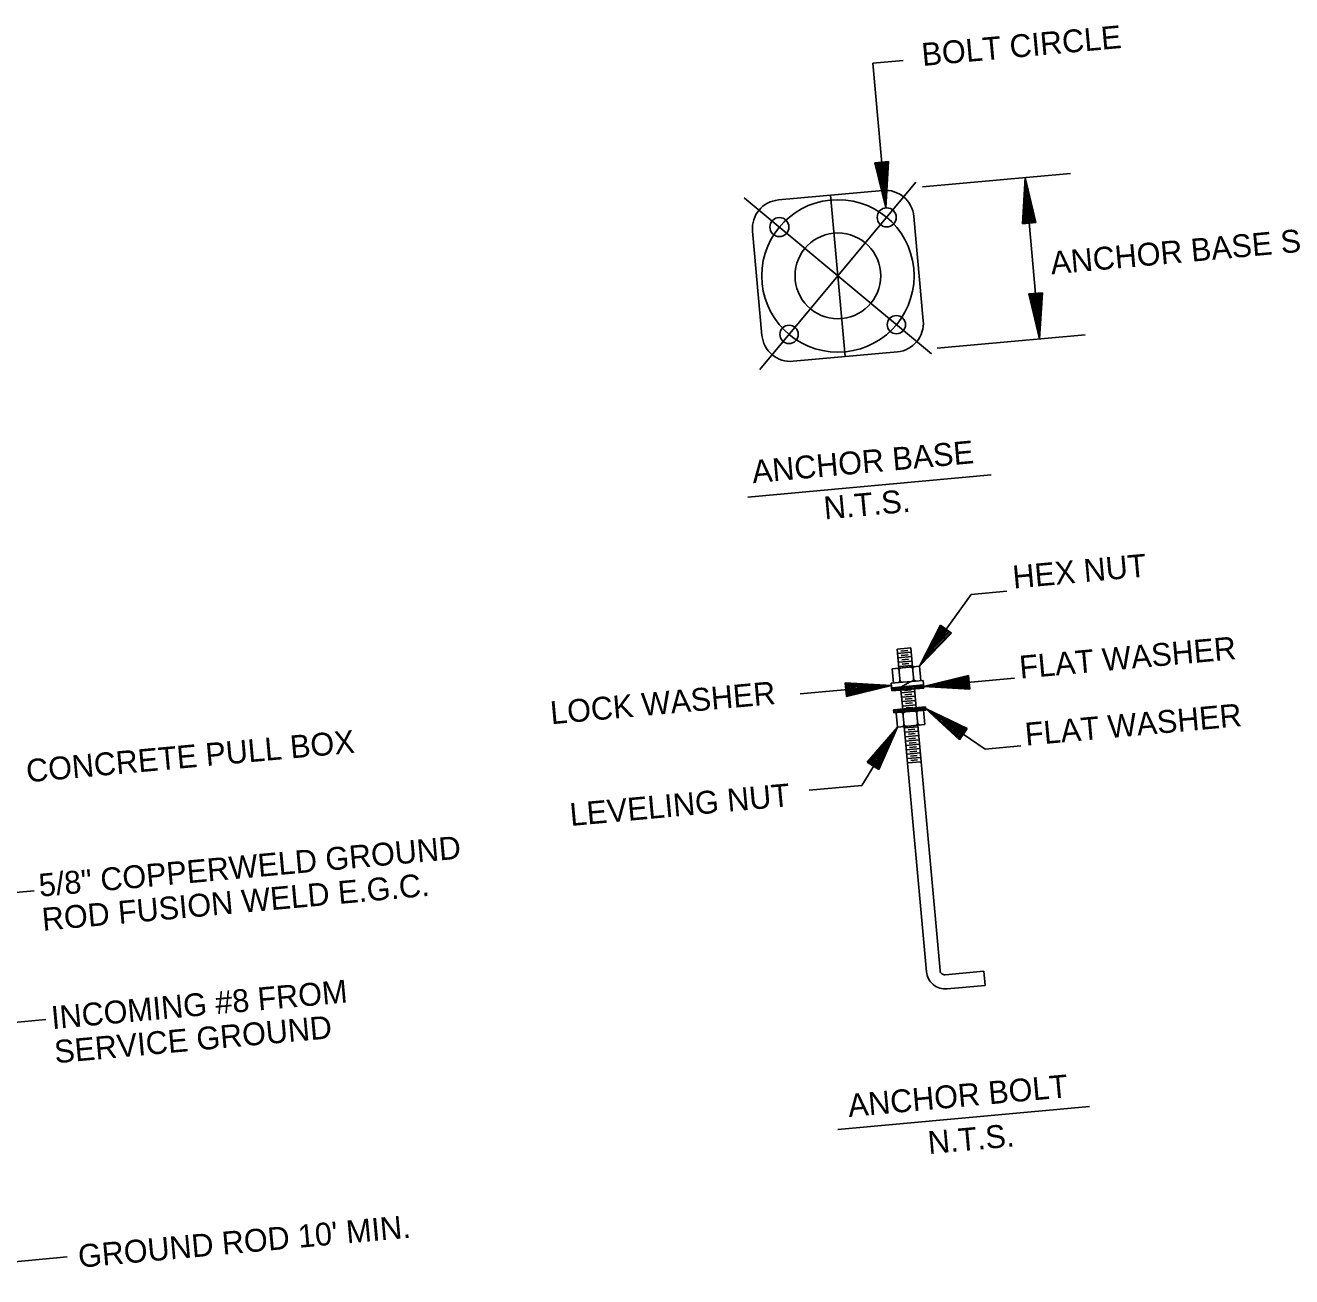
# Model space of a CAD drawing. Extents: x 1277218 to 1279252, y 196860 to 197529.
# Drawn here: x 1278535.3 to 1278789.6, y 197241.2 to 197492.4 of the extents above; entities that cross this region are included whole.
import ezdxf

# ---------------------------------------------------------------- set-up
doc = ezdxf.new("R2010")
doc.units = 0
doc.layers.add('R_Point Sym', color=7, linetype='Continuous')

msp = doc.modelspace()

# ---------------------------------------------------------------- linework, layer by layer
at = {"layer": 'R_Point Sym'}
for p, q in [((1278705.47, 197484.84), (1278711.6, 197485.39)), ((1278708.1, 197455.79), (1278705.47, 197484.84)), ((1278708.65, 197465.06), (1278705.91, 197464.81)), ((1278705.91, 197464.81), (1278708.1, 197455.79)), ((1278706.13, 197464.83), (1278707.97, 197457.32)), ((1278706.37, 197464.85), (1278707.82, 197458.89)), ((1278706.6, 197464.87), (1278707.69, 197460.41)), ((1278706.83, 197464.89), (1278707.55, 197461.96)), ((1278707.06, 197464.91), (1278707.41, 197463.49)), ((1278707.49, 197464.95), (1278707.41, 197463.49)), ((1278707.72, 197464.97), (1278707.55, 197461.96)), ((1278707.96, 197464.99), (1278707.69, 197460.41)), ((1278708.19, 197465.01), (1278707.82, 197458.89)), ((1278708.42, 197465.04), (1278707.97, 197457.32)), ((1278708.65, 197465.06), (1278708.1, 197455.79)), ((1278682.8, 197423.33), (1278714.16, 197460.94)), ((1278715.49, 197460), (1278745.2, 197462.69)), ((1278735.52, 197452.6), (1278736.06, 197461.86)), ((1278736.06, 197461.86), (1278738.99, 197429.48)), ((1278738.26, 197452.84), (1278736.06, 197461.86)), ((1278686.54, 197457.37), (1278707.49, 197459.27)), ((1278735.74, 197452.62), (1278736.2, 197460.33)), ((1278735.98, 197452.64), (1278736.34, 197458.76)), ((1278738.03, 197452.82), (1278736.2, 197460.33)), ((1278737.8, 197452.8), (1278736.34, 197458.76)), ((1278717.28, 197426.46), (1278679.68, 197457.81)), ((1278697.01, 197458.32), (1278699.95, 197425.94)), ((1278736.21, 197452.66), (1278736.48, 197457.24)), ((1278737.57, 197452.78), (1278736.48, 197457.24)), ((1278713.72, 197454.08), (1278715.62, 197433.13)), ((1278736.44, 197452.68), (1278736.62, 197455.69)), ((1278737.33, 197452.76), (1278736.62, 197455.69)), ((1278736.67, 197452.7), (1278736.76, 197454.16)), ((1278737.1, 197452.74), (1278736.76, 197454.16)), ((1278683.24, 197430.19), (1278681.34, 197451.14)), ((1278735.52, 197452.6), (1278738.26, 197452.84)), ((1278739.54, 197438.75), (1278736.79, 197438.5)), ((1278736.79, 197438.5), (1278738.99, 197429.48)), ((1278737.02, 197438.52), (1278738.85, 197431.01)), ((1278737.25, 197438.54), (1278738.71, 197432.58)), ((1278737.48, 197438.56), (1278738.57, 197434.1)), ((1278737.72, 197438.58), (1278738.43, 197435.65)), ((1278737.95, 197438.61), (1278738.29, 197437.18)), ((1278738.38, 197438.64), (1278738.29, 197437.18)), ((1278738.61, 197438.66), (1278738.43, 197435.65)), ((1278738.84, 197438.69), (1278738.57, 197434.1)), ((1278739.07, 197438.71), (1278738.71, 197432.58)), ((1278739.31, 197438.73), (1278738.85, 197431.01)), ((1278739.54, 197438.75), (1278738.99, 197429.48)), ((1278718.42, 197427.62), (1278748.13, 197430.31)), ((1278689.47, 197424.99), (1278710.42, 197426.89)), ((1278729.27, 197402.17), (1278680.42, 197397.74)), ((1278714.86, 197363.77), (1278725.24, 197378.19)), ((1278725.24, 197378.19), (1278732.39, 197378.84)), ((1278719.08, 197372.04), (1278714.86, 197363.77)), ((1278719.27, 197371.91), (1278715.75, 197365.02)), ((1278721.32, 197370.44), (1278719.08, 197372.04)), ((1278721.32, 197370.44), (1278714.86, 197363.77)), ((1278721.13, 197370.57), (1278715.75, 197365.02)), ((1278719.46, 197371.77), (1278716.67, 197366.3)), ((1278720.94, 197370.71), (1278716.67, 197366.3)), ((1278719.65, 197371.64), (1278717.56, 197367.55)), ((1278720.76, 197370.84), (1278717.56, 197367.55)), ((1278719.84, 197371.5), (1278718.47, 197368.81)), ((1278720.56, 197370.98), (1278718.47, 197368.81)), ((1278720.03, 197371.36), (1278719.36, 197370.06)), ((1278720.38, 197371.11), (1278719.36, 197370.06)), ((1278710.4, 197367.21), (1278713.14, 197367.46)), ((1278710.75, 197363.4), (1278710.4, 197367.21)), ((1278711.13, 197366.81), (1278712.5, 197366.94)), ((1278713.49, 197363.65), (1278713.14, 197367.46)), ((1278710.48, 197366.33), (1278713.22, 197366.58)), ((1278710.56, 197365.45), (1278713.3, 197365.7)), ((1278710.64, 197364.57), (1278713.38, 197364.82)), ((1278711.21, 197365.94), (1278712.58, 197366.06)), ((1278711.29, 197365.06), (1278712.66, 197365.18)), ((1278711.37, 197364.18), (1278712.74, 197364.3)), ((1278709.37, 197363.28), (1278714.86, 197363.77)), ((1278709.64, 197360.39), (1278709.37, 197363.28)), ((1278710.72, 197363.69), (1278713.46, 197363.94)), ((1278711.01, 197360.51), (1278710.75, 197363.4)), ((1278713.75, 197360.76), (1278713.49, 197363.65)), ((1278715.12, 197360.89), (1278714.86, 197363.77)), ((1278724.71, 197361.9), (1278715.69, 197359.7)), ((1278724.96, 197359.16), (1278724.71, 197361.9)), ((1278690.94, 197358.23), (1278709.22, 197359.89)), ((1278699.95, 197360.43), (1278709.22, 197359.89)), ((1278699.95, 197360.43), (1278700.2, 197357.69)), ((1278699.97, 197360.2), (1278707.69, 197359.75)), ((1278700, 197359.97), (1278706.12, 197359.61)), ((1278700.02, 197359.74), (1278704.6, 197359.47)), ((1278700.04, 197359.5), (1278703.05, 197359.33)), ((1278700.06, 197359.27), (1278701.52, 197359.19)), ((1278700.1, 197358.84), (1278701.52, 197359.19)), ((1278700.12, 197358.61), (1278703.05, 197359.33)), ((1278700.14, 197358.38), (1278704.6, 197359.47)), ((1278700.16, 197358.15), (1278706.12, 197359.61)), ((1278700.18, 197357.92), (1278707.69, 197359.75)), ((1278700.2, 197357.69), (1278709.22, 197359.89)), ((1278709.18, 197360.35), (1278715.58, 197360.93)), ((1278709.32, 197358.82), (1278709.18, 197360.35)), ((1278709.26, 197359.43), (1278715.66, 197360.01)), ((1278709.28, 197359.17), (1278709.52, 197359.45)), ((1278709.31, 197358.85), (1278709.84, 197359.48)), ((1278715.72, 197359.4), (1278709.32, 197358.82)), ((1278709.61, 197358.85), (1278710.16, 197359.51)), ((1278709.93, 197358.88), (1278710.49, 197359.54)), ((1278710.26, 197358.9), (1278710.81, 197359.57)), ((1278710.58, 197358.93), (1278711.13, 197359.6)), ((1278710.9, 197358.96), (1278711.46, 197359.63)), ((1278711.1, 197359.59), (1278713.02, 197360.67)), ((1278711.23, 197358.99), (1278711.78, 197359.66)), ((1278711.55, 197359.02), (1278712.1, 197359.69)), ((1278711.87, 197359.05), (1278712.43, 197359.72)), ((1278712.19, 197359.08), (1278712.75, 197359.74)), ((1278712.52, 197359.11), (1278713.07, 197359.77)), ((1278712.84, 197359.14), (1278713.4, 197359.8)), ((1278713.16, 197359.17), (1278713.72, 197359.83)), ((1278713.49, 197359.2), (1278714.04, 197359.86)), ((1278713.81, 197359.23), (1278714.37, 197359.89)), ((1278714.23, 197355.42), (1278713.89, 197359.23)), ((1278714.13, 197359.26), (1278714.69, 197359.92)), ((1278714.46, 197359.29), (1278715.01, 197359.95)), ((1278714.78, 197359.31), (1278715.34, 197359.98)), ((1278715.1, 197359.34), (1278715.66, 197360.01)), ((1278715.43, 197359.37), (1278715.69, 197359.69)), ((1278715.72, 197359.4), (1278715.58, 197360.93)), ((1278715.69, 197359.7), (1278733.97, 197361.36)), ((1278724.96, 197359.16), (1278715.69, 197359.7)), ((1278724.73, 197361.68), (1278717.22, 197359.84)), ((1278724.94, 197359.39), (1278717.22, 197359.84)), ((1278724.75, 197361.44), (1278718.79, 197359.98)), ((1278724.91, 197359.62), (1278718.79, 197359.98)), ((1278724.77, 197361.21), (1278720.31, 197360.12)), ((1278724.89, 197359.85), (1278720.31, 197360.12)), ((1278724.79, 197360.98), (1278721.86, 197360.26)), ((1278724.87, 197360.09), (1278721.86, 197360.26)), ((1278724.81, 197360.75), (1278723.39, 197360.4)), ((1278724.85, 197360.32), (1278723.39, 197360.4)), ((1278711.49, 197355.18), (1278711.15, 197358.99)), ((1278711.2, 197358.42), (1278713.94, 197358.67)), ((1278711.28, 197357.54), (1278714.02, 197357.79)), ((1278711.36, 197356.66), (1278714.1, 197356.91)), ((1278711.84, 197358.9), (1278713.22, 197359.03)), ((1278711.92, 197358.02), (1278713.3, 197358.15)), ((1278712, 197357.14), (1278713.37, 197357.27)), ((1278709.66, 197355.01), (1278716.06, 197355.59)), ((1278709.72, 197354.4), (1278709.66, 197355.01)), ((1278709.69, 197354.7), (1278709.97, 197355.04)), ((1278709.72, 197354.4), (1278716.12, 197354.98)), ((1278709.74, 197354.4), (1278710.29, 197355.07)), ((1278710.06, 197354.43), (1278710.62, 197355.1)), ((1278710.44, 197351.55), (1278710.17, 197354.44)), ((1278710.39, 197354.46), (1278710.94, 197355.13)), ((1278710.71, 197354.49), (1278711.26, 197355.16)), ((1278711.03, 197354.52), (1278711.59, 197355.18)), ((1278711.36, 197354.55), (1278711.91, 197355.21)), ((1278711.44, 197355.78), (1278714.18, 197356.03)), ((1278711.81, 197351.68), (1278711.55, 197354.57)), ((1278711.68, 197354.58), (1278712.23, 197355.24)), ((1278712, 197354.61), (1278712.56, 197355.27)), ((1278712.08, 197356.27), (1278713.45, 197356.39)), ((1278712.16, 197355.39), (1278713.53, 197355.51)), ((1278712.33, 197354.64), (1278712.88, 197355.3)), ((1278712.65, 197354.67), (1278713.2, 197355.33)), ((1278712.97, 197354.7), (1278713.53, 197355.36)), ((1278713.3, 197354.72), (1278713.85, 197355.39)), ((1278713.62, 197354.75), (1278714.17, 197355.42)), ((1278713.94, 197354.78), (1278714.5, 197355.45)), ((1278714.27, 197354.81), (1278714.82, 197355.48)), ((1278714.55, 197351.93), (1278714.29, 197354.81)), ((1278714.59, 197354.84), (1278715.14, 197355.51)), ((1278714.91, 197354.87), (1278715.47, 197355.54)), ((1278715.24, 197354.9), (1278715.79, 197355.57)), ((1278715.56, 197354.93), (1278716.07, 197355.54)), ((1278715.92, 197352.05), (1278715.66, 197354.94)), ((1278715.88, 197354.96), (1278716.1, 197355.22)), ((1278716.12, 197354.98), (1278716.06, 197355.59)), ((1278716.09, 197355.29), (1278728.06, 197347.12)), ((1278722.9, 197348.98), (1278716.09, 197355.29)), ((1278724.45, 197351.26), (1278716.09, 197355.29)), ((1278723.03, 197349.17), (1278717.36, 197354.42)), ((1278724.32, 197351.07), (1278717.36, 197354.42)), ((1278710.44, 197351.55), (1278703.26, 197339.85)), ((1278704.39, 197344.51), (1278710.44, 197351.55)), ((1278706.72, 197343.05), (1278710.44, 197351.55)), ((1278710.44, 197351.55), (1278715.92, 197352.05)), ((1278716.27, 197302.45), (1278711.81, 197351.68)), ((1278711.83, 197351.39), (1278714.58, 197351.63)), ((1278719.01, 197302.66), (1278714.55, 197351.93)), ((1278724.19, 197350.87), (1278718.66, 197353.53)), ((1278723.16, 197349.36), (1278718.66, 197353.53)), ((1278723.29, 197349.55), (1278719.93, 197352.67)), ((1278724.06, 197350.68), (1278719.93, 197352.67)), ((1278723.93, 197350.49), (1278721.21, 197351.8)), ((1278723.43, 197349.75), (1278721.21, 197351.8)), ((1278704.58, 197344.39), (1278709.62, 197350.26)), ((1278706.53, 197343.17), (1278709.62, 197350.26)), ((1278711.91, 197350.51), (1278714.66, 197350.76)), ((1278711.99, 197349.63), (1278714.74, 197349.88)), ((1278712.07, 197348.75), (1278714.82, 197349)), ((1278712.56, 197350.99), (1278713.93, 197351.12)), ((1278712.64, 197350.11), (1278714.01, 197350.24)), ((1278712.72, 197349.23), (1278714.09, 197349.36)), ((1278723.8, 197350.3), (1278722.48, 197350.93)), ((1278723.56, 197349.94), (1278722.48, 197350.93)), ((1278722.9, 197348.98), (1278724.45, 197351.26)), ((1278704.78, 197344.26), (1278708.78, 197348.92)), ((1278704.98, 197344.14), (1278707.97, 197347.62)), ((1278706.14, 197343.42), (1278707.97, 197347.62)), ((1278706.33, 197343.29), (1278708.78, 197348.92)), ((1278712.15, 197347.87), (1278714.9, 197348.12)), ((1278712.23, 197346.99), (1278714.98, 197347.24)), ((1278712.8, 197348.35), (1278714.17, 197348.48)), ((1278712.88, 197347.47), (1278714.25, 197347.6)), ((1278712.96, 197346.6), (1278714.33, 197346.72)), ((1278728.06, 197347.12), (1278735.2, 197347.77)), ((1278704.39, 197344.51), (1278706.72, 197343.05)), ((1278705.18, 197344.02), (1278707.14, 197346.31)), ((1278705.37, 197343.89), (1278706.33, 197345.01)), ((1278705.74, 197343.66), (1278706.33, 197345.01)), ((1278705.94, 197343.54), (1278707.14, 197346.31)), ((1278712.31, 197346.11), (1278715.05, 197346.36)), ((1278712.39, 197345.23), (1278715.13, 197345.48)), ((1278712.47, 197344.35), (1278715.21, 197344.6)), ((1278713.04, 197345.72), (1278714.41, 197345.84)), ((1278713.12, 197344.84), (1278714.49, 197344.96)), ((1278692.69, 197338.89), (1278703.26, 197339.85)), ((1278494.14, 197314.79), (1278537.09, 197318.68)), ((1278720.01, 197301.83), (1278727.78, 197302.53)), ((1278728.04, 197299.68), (1278727.78, 197302.53)), ((1278720.42, 197298.99), (1278728.04, 197299.68)), ((1278521.01, 197291.16), (1278539.43, 197292.83)), ((1278749.01, 197275.37), (1278698.49, 197270.79)), ((1278500.21, 197241.23), (1278543.75, 197245.18))]:
    msp.add_line(p, q, dxfattribs=at)
for centre, radius in [((1278698.48, 197442.13), 15.3), ((1278708.28, 197453.88), 1.91), ((1278686.73, 197451.93), 1.91), ((1278698.48, 197442.13), 8.61), ((1278710.23, 197432.34), 1.84), ((1278688.68, 197430.38), 1.84)]:
    msp.add_circle(centre, radius, dxfattribs=at)
for centre, radius, start, end in [((1278708.01, 197453.56), 5.74, 5.1779, 95.1779), ((1278687.05, 197451.66), 5.74, 95.1779, 185.1779), ((1278709.9, 197432.61), 5.74, 275.1779, 5.1779), ((1278688.95, 197430.71), 5.74, 185.1779, 275.1779), ((1278710.33, 197362.9), 0.459, 5.1779, 95.1779), ((1278711.24, 197362.98), 0.459, 95.1779, 185.1779), ((1278713.07, 197363.15), 0.459, 5.1779, 95.1779), ((1278713.99, 197363.23), 0.459, 95.1779, 185.1779), ((1278710.51, 197360.93), 0.459, 275.1779, 5.1779), ((1278711.42, 197361.01), 0.459, 185.1779, 275.1779), ((1278713.25, 197361.18), 0.459, 275.1779, 5.1779), ((1278714.17, 197361.26), 0.459, 185.1779, 275.1779), ((1278711.13, 197354.07), 0.459, 5.1779, 95.1779), ((1278712.04, 197354.15), 0.459, 95.1779, 185.1779), ((1278713.87, 197354.32), 0.459, 5.1779, 95.1779), ((1278714.79, 197354.4), 0.459, 95.1779, 185.1779), ((1278711.31, 197352.09), 0.459, 275.1779, 5.1779), ((1278712.22, 197352.18), 0.459, 185.1779, 275.1779), ((1278714.05, 197352.34), 0.459, 275.1779, 5.1779), ((1278714.97, 197352.43), 0.459, 185.1779, 275.1779), ((1278720.08, 197302.8), 3.82, 185.1779, 275.1779), ((1278719.93, 197302.74), 0.918, 185.1779, 275.1779)]:
    msp.add_arc(centre, radius, start, end, dxfattribs=at)

# ---------------------------------------------------------------- texts
for s, height, p in [('BOLT CIRCLE', 4.5899, (1278715.5, 197484.26)), ('ANCHOR BASE SQUARE', 4.5899, (1278741.37, 197442.42)), ('ANCHOR BASE', 4.5899, (1278681.43, 197400.51)), ('N.T.S.', 4.59, (1278695.85, 197393.22)), ('HEX NUT', 4.59, (1278733.77, 197379.36)), ('FLAT WASHER', 4.5899, (1278735.13, 197361.27)), ('LOCK WASHER', 4.5899, (1278640.93, 197352.11)), ('FLAT WASHER', 4.5899, (1278736.25, 197347.82)), ('CONCRETE PULL BOX', 4.5899, (1278535.7, 197340.45)), ('LEVELING NUT', 4.5899, (1278644.85, 197331.69)), ('5/8" COPPERWELD GROUND ', 4.5899, (1278538.24, 197317.5)), ('ROD FUSION WELD E.G.C.', 4.5899, (1278538.86, 197310.65)), ('INCOMING #8 FROM ', 4.5899, (1278540.73, 197290.91)), ('SERVICE GROUND', 4.5899, (1278541.35, 197284.06)), ('ANCHOR BOLT', 4.5899, (1278700.7, 197273.27)), ('N.T.S.', 4.59, (1278716.75, 197265.83)), ("GROUND ROD 10' MIN.", 4.5899, (1278546.13, 197243.02))]:
    msp.add_text(s, height=height, rotation=5.1779, dxfattribs=at).set_placement(p)

doc.saveas('drawing.dxf')
